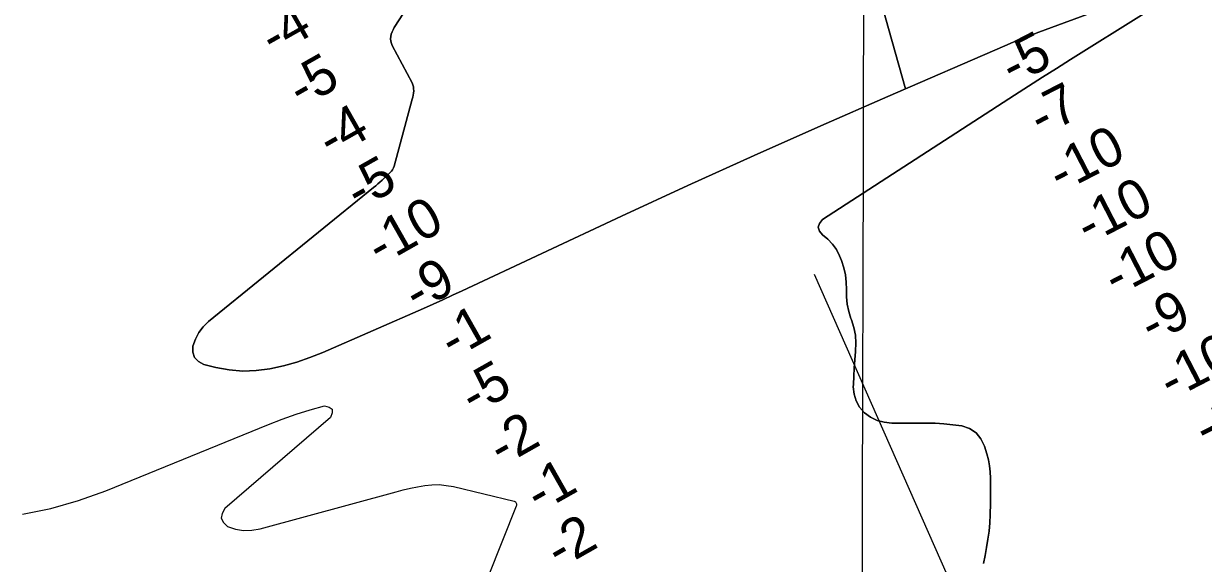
# Model space of a CAD drawing. Extents: x 3177385 to 3215275, y 903885 to 929304.
# Drawn here: x 3190624 to 3192634, y 910956 to 911876 of the extents above; entities that cross this region are included whole.
import ezdxf

# ---------------------------------------------------------------- set-up
doc = ezdxf.new("R2010")
doc.units = 0
for name, color, linetype in [('V-GRID-MAJR', 7, 'Continuous'), ('V-RIVR-RANG', 7, 'Continuous'), ('V-TOPO-DPTH', 7, 'Continuous'), ('V-TOPO-MINR', 7, 'Continuous')]:
    doc.layers.add(name, color=color, linetype=linetype)

msp = doc.modelspace()

# ---------------------------------------------------------------- linework, layer by layer
at = {"layer": 'V-GRID-MAJR'}
msp.add_spline([(3192048.7, 909312.8), (3192063.7, 915372.6), (3192078.7, 921435.5), (3192093.7, 927498.5), (3192093.7, 927501.6)], degree=3, dxfattribs=at)
at = {"layer": 'V-RIVR-RANG'}
msp.add_line((3192335.4, 910625.2), (3191971.4, 911448.3), dxfattribs=at)
at = {"layer": 'V-TOPO-DPTH'}
for points in [[(3192137.1, 911769.6), (3192126.1, 911764.9), (3192069.8, 911967.1), (3192078.1, 911970.5), (3192169.3, 912008.2), (3192198.2, 912020.6), (3192226.9, 912033.4), (3192255.2, 912047), (3192283.3, 912061), (3192654.8, 912252.6), (3192694.9, 912276.1), (3192733.2, 912302), (3192768.6, 912331.8), (3192802.1, 912364.1), (3192859.9, 912426), (3192861.9, 912429.4), (3192863, 912432.9)], [(3192549.2, 911934.3), (3192353.7, 911861.6), (3192339, 911856), (3192324.4, 911850.3), (3192309.9, 911844.3), (3192295.5, 911838.2), (3192096.1, 911751.9), (3191982.3, 911702), (3191868.7, 911651.5), (3191755.6, 911599.9), (3191642.7, 911547.8), (3191370.8, 911420.6), (3191354.4, 911413), (3191338, 911405.5), (3191321.5, 911398.1), (3191305.1, 911390.8), (3191133.5, 911315.8), (3191111.5, 911307), (3191089.3, 911299.3), (3191066.6, 911293.1), (3191043.5, 911287.8), (3191043.3, 911287.8), (3191020.2, 911284.9), (3190997.1, 911284), (3190974.2, 911286.1), (3190951.3, 911290.2), (3190930.7, 911295.2), (3190921.5, 911300.3), (3190914.8, 911307), (3190912.1, 911316), (3190912.1, 911326.6), (3190916.5, 911338.5), (3190922.2, 911349.5), (3190929.8, 911359.3), (3190938.9, 911368.2), (3191219.8, 911596.5), (3191223.6, 911599.6), (3191227.3, 911602.8), (3191230.9, 911606), (3191234.5, 911609.3), (3191249.5, 911623.4), (3191250.5, 911624.4), (3191252.1, 911626.6), (3191254, 911630.4), (3191254.9, 911633.1), (3191285.8, 911747.2), (3191286.7, 911750.7), (3191287.4, 911754.2), (3191287.9, 911757.7), (3191288.3, 911761.3), (3191288.2, 911764.8), (3191287.8, 911768.2), (3191286.8, 911771.5), (3191285.5, 911774.8), (3191251.9, 911838.6), (3191250.4, 911842.3), (3191249.4, 911846.1), (3191249.1, 911850), (3191249.3, 911854), (3191250.2, 911858), (3191251.4, 911861.8), (3191253.1, 911865.5), (3191255.1, 911869.1), (3191322.7, 911973.6)], [(3192126.1, 911764.9), (3192096.1, 911751.9), (3191982.3, 911702), (3191868.7, 911651.5), (3191755.6, 911599.9), (3191642.7, 911547.8), (3191370.8, 911420.6), (3191354.4, 911413), (3191338, 911405.5), (3191321.5, 911398.1), (3191305.1, 911390.8), (3191133.5, 911315.8), (3191111.5, 911307), (3191089.3, 911299.3), (3191066.6, 911293.1), (3191043.5, 911287.8), (3191043.3, 911287.8), (3191020.2, 911284.9), (3190997.1, 911284), (3190974.2, 911286.1), (3190951.3, 911290.2), (3190930.7, 911295.2), (3190921.5, 911300.3), (3190914.8, 911307), (3190912.1, 911316), (3190912.1, 911326.6), (3190916.5, 911338.5), (3190922.2, 911349.5), (3190929.8, 911359.3), (3190938.9, 911368.2), (3191219.8, 911596.5), (3191223.6, 911599.6), (3191227.3, 911602.8), (3191230.9, 911606), (3191234.5, 911609.3), (3191249.5, 911623.4), (3191250.5, 911624.4), (3191252.1, 911626.6), (3191254, 911630.4), (3191254.9, 911633.1), (3191285.8, 911747.2), (3191286.7, 911750.7), (3191287.4, 911754.2), (3191287.9, 911757.7), (3191288.3, 911761.3), (3191288.2, 911764.8), (3191287.8, 911768.2), (3191286.8, 911771.5), (3191285.5, 911774.8), (3191251.9, 911838.6), (3191250.4, 911842.3), (3191249.4, 911846.1), (3191249.1, 911850), (3191249.3, 911854), (3191250.2, 911858), (3191251.4, 911861.8), (3191253.1, 911865.5), (3191255.1, 911869.1), (3191322.7, 911973.6)], [(3192069.8, 911967.1), (3192126.1, 911764.9)], [(3192549.2, 911934.3), (3192353.7, 911861.6), (3192339, 911856), (3192324.4, 911850.3), (3192309.9, 911844.3), (3192295.5, 911838.2), (3192137.1, 911769.6)], [(3192259.1, 910955.8), (3192261.8, 910969.6), (3192264.5, 910983.4), (3192266.8, 910997.3), (3192268.7, 911011.2), (3192269.8, 911025.2), (3192270.5, 911039.2), (3192270.9, 911059), (3192271.1, 911069.6), (3192271.2, 911080.2), (3192271.2, 911090.8), (3192271.2, 911101.5), (3192270.6, 911112), (3192269.5, 911122.5), (3192267.5, 911132.9), (3192264.9, 911143.1), (3192261, 911156.2), (3192254.7, 911168.7), (3192246.5, 911178.9), (3192235.3, 911185.8), (3192222.1, 911190.4), (3192207, 911192.5), (3192191.9, 911194.1), (3192176.7, 911195), (3192161.5, 911195.3), (3192102.9, 911195.2), (3192090.2, 911196.7), (3192078, 911199.8), (3192066.9, 911205.5), (3192056.4, 911212.9), (3192048.2, 911222.5), (3192042, 911233), (3192038.7, 911244.7), (3192037.4, 911257.3), (3192037.5, 911260.8), (3192038.2, 911275), (3192039, 911289.1), (3192040.1, 911303.2), (3192041.3, 911317.3), (3192041.4, 911317.9), (3192041.8, 911331.6), (3192040.9, 911345.1), (3192038.1, 911358.3), (3192034.1, 911371.4), (3192033.3, 911373.5), (3192029.5, 911385.5), (3192026.8, 911397.7), (3192025.7, 911410.2), (3192025.6, 911422.8), (3192025.5, 911435.5), (3192024.3, 911447.9), (3192021.4, 911460.1), (3192017.5, 911472.1), (3192014.1, 911480.3), (3192008.6, 911490.8), (3192002.1, 911500.3), (3191994, 911508.5), (3191984.8, 911515.8), (3191979.9, 911522.4), (3191977.7, 911529), (3191979.9, 911535.6), (3191984.9, 911542.1), (3192312, 911753.9), (3192335.8, 911769.2), (3192359.6, 911784.5), (3192383.5, 911799.6), (3192407.4, 911814.6), (3192533.2, 911893.3)], [(3192259.1, 910955.8), (3192261.8, 910969.6), (3192264.5, 910983.4), (3192266.8, 910997.3), (3192268.7, 911011.2), (3192269.8, 911025.2), (3192270.5, 911039.2), (3192270.9, 911059), (3192271.1, 911069.6), (3192271.2, 911080.2), (3192271.2, 911090.8), (3192271.2, 911101.5), (3192270.6, 911112), (3192269.5, 911122.5), (3192267.5, 911132.9), (3192264.9, 911143.1), (3192261, 911156.2), (3192254.7, 911168.7), (3192246.5, 911178.9), (3192235.3, 911185.8), (3192222.1, 911190.4), (3192207, 911192.5), (3192191.9, 911194.1), (3192176.7, 911195), (3192161.5, 911195.3), (3192102.9, 911195.2), (3192090.2, 911196.7), (3192078, 911199.8), (3192066.9, 911205.5), (3192056.4, 911212.9), (3192048.2, 911222.5), (3192042, 911233), (3192038.7, 911244.7), (3192037.4, 911257.3), (3192037.5, 911260.8), (3192038.2, 911275), (3192039, 911289.1), (3192040.1, 911303.2), (3192041.3, 911317.3), (3192041.4, 911317.9), (3192041.8, 911331.6), (3192040.9, 911345.1), (3192038.1, 911358.3), (3192034.1, 911371.4), (3192033.3, 911373.5), (3192029.5, 911385.5), (3192026.8, 911397.7), (3192025.7, 911410.2), (3192025.6, 911422.8), (3192025.5, 911435.5), (3192024.3, 911447.9), (3192021.4, 911460.1), (3192017.5, 911472.1), (3192014.1, 911480.3), (3192008.6, 911490.8), (3192002.1, 911500.3), (3191994, 911508.5), (3191984.8, 911515.8), (3191979.9, 911522.4), (3191977.7, 911529), (3191979.9, 911535.6), (3191984.9, 911542.1), (3192312, 911753.9), (3192335.8, 911769.2), (3192359.6, 911784.5), (3192383.5, 911799.6), (3192407.4, 911814.6), (3192533.2, 911893.3)]]:
    msp.add_lwpolyline(points, dxfattribs=at)
at = {"layer": 'V-TOPO-MINR'}
for points in [[(3191322.7, 911973.6), (3191255.1, 911869.1), (3191253.1, 911865.5), (3191251.4, 911861.8), (3191250.2, 911858), (3191249.3, 911854), (3191249.1, 911850), (3191249.4, 911846.1), (3191250.4, 911842.3), (3191251.9, 911838.6), (3191285.5, 911774.8), (3191286.8, 911771.5), (3191287.8, 911768.2), (3191288.2, 911764.8), (3191288.3, 911761.3), (3191287.9, 911757.7), (3191287.4, 911754.2), (3191286.7, 911750.7), (3191285.8, 911747.2), (3191254.9, 911633.1), (3191254, 911630.4), (3191252.1, 911626.6), (3191250.5, 911624.4), (3191249.5, 911623.4), (3191234.5, 911609.3), (3191230.9, 911606), (3191227.3, 911602.8), (3191223.6, 911599.6), (3191219.8, 911596.5), (3190938.9, 911368.2), (3190929.8, 911359.3), (3190922.2, 911349.5), (3190916.5, 911338.5), (3190912.1, 911326.6), (3190912.1, 911316), (3190914.8, 911307), (3190921.5, 911300.3), (3190930.7, 911295.2), (3190951.3, 911290.2), (3190974.2, 911286.1), (3190997.1, 911284), (3191020.2, 911284.9), (3191043.3, 911287.8), (3191043.5, 911287.8), (3191066.6, 911293.1), (3191089.3, 911299.3), (3191111.5, 911307), (3191133.5, 911315.8), (3191305.1, 911390.8), (3191321.5, 911398.1), (3191338, 911405.5), (3191354.4, 911413), (3191370.8, 911420.6), (3191642.7, 911547.8), (3191755.6, 911599.9), (3191868.7, 911651.5), (3191982.3, 911702), (3192096.1, 911751.9), (3192295.5, 911838.2), (3192309.9, 911844.3), (3192324.4, 911850.3), (3192339, 911856), (3192353.7, 911861.6), (3192549.2, 911934.3)], [(3192533.2, 911893.3), (3192407.4, 911814.6), (3192383.5, 911799.6), (3192359.6, 911784.5), (3192335.8, 911769.2), (3192312, 911753.9), (3191984.9, 911542.1), (3191979.9, 911535.6), (3191977.7, 911529), (3191979.9, 911522.4), (3191984.8, 911515.8), (3191994, 911508.5), (3192002.1, 911500.3), (3192008.6, 911490.8), (3192014.1, 911480.3), (3192017.5, 911472.1), (3192021.4, 911460.1), (3192024.3, 911447.9), (3192025.5, 911435.5), (3192025.6, 911422.8), (3192025.7, 911410.2), (3192026.8, 911397.7), (3192029.5, 911385.5), (3192033.3, 911373.5), (3192034.1, 911371.4), (3192038.1, 911358.3), (3192040.9, 911345.1), (3192041.8, 911331.6), (3192041.4, 911317.9), (3192041.3, 911317.3), (3192040.1, 911303.2), (3192039, 911289.1), (3192038.2, 911275), (3192037.5, 911260.8), (3192037.4, 911257.3), (3192038.7, 911244.7), (3192042, 911233), (3192048.2, 911222.5), (3192056.4, 911212.9), (3192066.9, 911205.5), (3192078, 911199.8), (3192090.2, 911196.7), (3192102.9, 911195.2), (3192161.5, 911195.3), (3192176.7, 911195), (3192191.9, 911194.1), (3192207, 911192.5), (3192222.1, 911190.4), (3192235.3, 911185.8), (3192246.5, 911178.9), (3192254.7, 911168.7), (3192261, 911156.2), (3192264.9, 911143.1), (3192267.5, 911132.9), (3192269.5, 911122.5), (3192270.6, 911112), (3192271.2, 911101.5), (3192271.2, 911090.8), (3192271.2, 911080.2), (3192271.1, 911069.6), (3192270.9, 911059), (3192270.5, 911039.2), (3192269.8, 911025.2), (3192268.7, 911011.2), (3192266.8, 910997.3), (3192264.5, 910983.4), (3192261.8, 910969.6), (3192259.1, 910955.8)], [(3190622, 911040.1), (3190670.2, 911049.7), (3190717.4, 911063.6), (3190763.9, 911080.1), (3191041.1, 911193), (3191064.5, 911202), (3191088.2, 911210.4), (3191112.1, 911217.8), (3191136.2, 911224.7), (3191144.4, 911222.6), (3191149.4, 911218.9), (3191149.7, 911212.6), (3191146.7, 911204.7), (3190966.6, 911049.9), (3190961.8, 911041.3), (3190960.4, 911033.2), (3190964.1, 911025.8), (3190971.2, 911019), (3190984.8, 911014.7), (3190998.6, 911012.3), (3191012.5, 911012.7), (3191026.6, 911015), (3191258.6, 911078.3), (3191270.6, 911081.4), (3191282.7, 911084.2), (3191294.9, 911086.7), (3191307.2, 911088.9), (3191319.4, 911090.1), (3191331.6, 911090.4), (3191343.8, 911089.2), (3191355.9, 911087.1), (3191459.4, 911062.1), (3191461.6, 911060.9), (3191462.4, 911060), (3191463.3, 911057.5), (3191463.3, 911054.9), (3191462.9, 911053.6), (3191415.4, 910933.7)]]:
    msp.add_lwpolyline(points, dxfattribs=at)

# ---------------------------------------------------------------- texts
at = {"layer": 'V-RIVR-RANG'}
for s, rotation, p in [('-4', 29.5319, (3191049.6, 911819.5)), ('-5', 27.3247, (3192309.2, 911769.9)), ('-5', 29.5319, (3191097, 911731.4)), ('-7', 27.3247, (3192357.6, 911682.4)), ('-4', 29.5319, (3191147.5, 911645.1)), ('-10', 27.3247, (3192390.4, 911586.8)), ('-5', 29.5319, (3191194.8, 911556.9)), ('-10', 27.3247, (3192437.5, 911498.5)), ('-10', 29.5319, (3191231.1, 911462.6)), ('-10', 27.3247, (3192484.6, 911410.3)), ('-9', 29.5319, (3191294.3, 911383.4)), ('-9', 27.3247, (3192546.2, 911329.6)), ('-1', 29.5319, (3191355.1, 911303)), ('-10', 27.3247, (3192578.7, 911233.8)), ('-5', 29.5319, (3191390.5, 911208.1)), ('-11', 27.3247, (3192638.9, 911152.4)), ('-2', 29.5319, (3191438.5, 911120.3)), ('-1', 29.5319, (3191501.9, 911041.3)), ('-2', 29.5319, (3191536.4, 910945.9))]:
    msp.add_text(s, height=67, rotation=rotation, dxfattribs=at).set_placement(p)

doc.saveas('drawing.dxf')
